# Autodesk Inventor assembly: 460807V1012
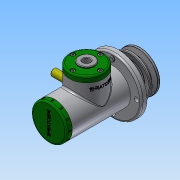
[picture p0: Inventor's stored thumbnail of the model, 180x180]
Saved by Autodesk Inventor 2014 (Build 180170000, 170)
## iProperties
Created: 2016-08
Part Number: 460807V1012
Document SubType Name: Assembly
Designer: NET
Author: NET
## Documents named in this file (21)
- C:\Users\NET\Desktop\460807V1012\460807V1012.iam
- C:\Users\NET\Desktop\460807V1012\V-벨트풀리.ipt
- C:\Users\NET\Desktop\460807V1012\너트 M10.ipt
- C:\Users\NET\Desktop\460807V1012\링크.ipt
- C:\Users\NET\Desktop\460807V1012\베어링 15 x 35 x 11.ipt
- C:\Users\NET\Desktop\460807V1012\본체.ipt
- C:\Users\NET\Desktop\460807V1012\볼트 M4 x 10.ipt
- C:\Users\NET\Desktop\460807V1012\볼트 M4 x 12.ipt
- C:\Users\NET\Desktop\460807V1012\부시1.ipt
- C:\Users\NET\Desktop\460807V1012\부시2.ipt
- C:\Users\NET\Desktop\460807V1012\사이드 커버.ipt
- 사이드 커버.ipt
- C:\Users\NET\Desktop\460807V1012\슬라이더.ipt
- C:\Users\NET\Desktop\460807V1012\오일 실 15 25 7.ipt
- C:\Users\NET\Desktop\460807V1012\와셔 10x21.ipt
- C:\Users\NET\Desktop\460807V1012\클래스터 핀 6 x 24.ipt
- C:\Users\NET\Desktop\460807V1012\키 4 x 4 x 18.ipt
- C:\Users\NET\Desktop\460807V1012\탑 부시.ipt
- C:\Users\NET\Desktop\460807V1012\탑 커버.ipt
- 탑 커버.ipt
- C:\Users\NET\Desktop\460807V1012\편심축.ipt
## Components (7 placed, 3 different names)
1. V-벨트풀리:1 — 각도:2
2. ISO 4017 M4 x 10:1
3. ISO 4762 M4 x 12:1
4. ISO 4762 M4 x 12:3
5. ISO 4762 M4 x 12:4
6. ISO 4762 M4 x 12:5
7. ISO 4017 M4 x 10:2
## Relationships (1: Angle 1)
- 각도:2 [Angle]: V-벨트풀리:1
